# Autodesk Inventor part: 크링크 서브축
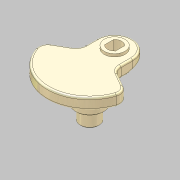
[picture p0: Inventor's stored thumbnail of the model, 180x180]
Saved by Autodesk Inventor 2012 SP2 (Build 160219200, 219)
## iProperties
Manager: KYOUNG IL JANG
Company: 한국ATC센터
Created: 2012-10
Part Number: 크링크 서브축
Document SubType Name: Modeling
Density: 1 g/cm^3
Checked By: KYOUNG IL JANG
Vendor: CBT Solutions
Designer: KYOUNG IL JANG
Material: 기본값
Author: KYOUNG IL JANG
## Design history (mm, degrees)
sketch "스케치1"
  geometry: L1 (-19, 109.368)-(-19, 91.368); L2 (-19, 91.368)-(-44.545, 76.619); L3 (19, 109.368)-(19, 91.368); L4 (19, 91.368)-(44.545, 76.619); C1 r 32.5 at (0, 83) reference; C2 r 10 at (0, 83); C3 r 17.5 at (0, 83); A1 r 45 centre (0, 83) between (-44.545, 76.619) and (44.545, 76.619); A2 r 32.5 centre (0, 83) between (-19, 109.368) and (19, 109.368); A3 r 19 centre (0, 109.368) between (19, 109.368) and (-19, 109.368); 1 further point
  constraints: 8 end point, 6 point on circle, 5 centre point, 4 coincident, 2 equal length, 1 horizontal alignment, 1 parallel, 1 tangent, 1 vertical, 1 vertical alignment
  dimensions: "d0" = 20 diameter of C2; "d1" = 35 diameter of C3; "d2" = 90 diameter of A1 (derived); "d3" = 65 diameter of A2 (derived); "d4" = 120 deg angle of L3 L4; "d5" = 19 radius of A3 (derived); "d6" = 18 distance of L1.start L1.end (derived)
  node "참조1"
extrude "돌출1" new body sketch "스케치1" distance "d7" = 12; taper "d8" = 0 deg
extrude "돌출2" join sketch "스케치1" distance "d9" = 5; taper "d10" = 0 deg
extrude "돌출3" join sketch "스케치1" distance "d11" = 41; taper "d12" = 0 deg
sketch "스케치2"
  geometry: C1 r 7.5 at (0, 109.368); C2 r 11 at (0, 109.368); A1 r 19 centre (0, 109.368) between (19, 109.368) and (-19, 109.368) reference; 1 further point
  constraints: 2 centre point, 2 coincident
  dimensions: "d13" = 15 diameter of C1; "d14" = 22 diameter of C2
extrude "돌출4" join sketch "스케치2" distance "d15" = 3; taper "d16" = 0 deg
extrude "돌출6" cut sketch "스케치2" stored distance "d19" = 10; taper "d20" = 0 deg
sketch "스케치3"
  geometry: L1 (-5.75, 4.815)-(-5.75, -4.815); L2 (5.75, 4.815)-(5.75, -4.815); A1 r 7.5 centre (0, 0) between (-5.75, 4.815) and (-5.75, -4.815) reference; 1 further point
  constraints: 4 end point, 4 point on circle, 2 parallel, 1 vertical
  dimensions: "d21" = 11.5 distance between parallel lines of L2 L1
extrude "돌출7" join sketch "스케치3" stored distance "d22" = 10; taper "d23" = 0 deg
sketch "스케치4"
  geometry: C1 r 10 at (0, 0) reference; C2 r 15 at (0, 0); 1 further point
  constraints: 1 centre point, 1 coincident
  dimensions: "d30" = 30 diameter of C2
extrude "돌출8" join sketch "스케치4" distance "d28" = 21; taper "d29" = 0 deg
chamfer "모따기1" distance "d31" = 1; stored, may be unused: second distance "d32" = 2, angle "d33" = 45 deg
sketch "스케치5"
  geometry: L1 (-19, 91.368)-(-19, 109.368) reference; L2 (19, 109.368)-(19, 91.368) reference; C1 r 9 at (0, 83); 3 further points
  constraints: 2 point on line, 1 centre point, 1 horizontal alignment
  dimensions: "d34" = 21 vertical distance of point (-19, 104) C1.centre (derived)
node "작업 평면1"
  node "작업축2"
sketch "스케치6"
  geometry: L1 (0, 50)-(38, 50); L2 (38, 50)-(38, 0); L3 (38, 0)-(0, 0); L4 (0, 0)-(0, 50); L5 (0, -12.202)-(0, 5.185) reference; L6 (38, 5.185)-(38, -12.202) reference; 2 further points
  constraints: 8 end point, 2 collinear, 1 point on line
  dimensions: "d37" = 50 distance from line of L1 L3.end
extrude "돌출9" cut sketch "스케치6" stored distance "d38" = 20.7; taper "d39" = 0 deg
fillet "모깎기1" dims "d26" = 10, "d27" = 2
node "솔리드1"
other parameters: "d35" = -15 deg (derived)
